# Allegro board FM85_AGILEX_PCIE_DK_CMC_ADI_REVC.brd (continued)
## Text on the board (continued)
User.45: R | PCB EDGE | Max component height bottom side | of PCIe card: .105/2.67mm | DWG NO. | SIZE | SCALE: 1/1 | REV | CAGE CODE | SHEET 2 OF 2 | PROPRIETARY NOTICE: | THIS DOCUMENT CONTAINS PROPRIETARY INFORMATION | OF ALTERA CORP. NEITHER THE DOCUMENT NOR SAID | PROPRIETARY INFORMATION SHALL BE PUBLISHED, | REPRODUCED, COPIED, DISCLOSED OR USED FOR ANY | PURPOSE OTHER THAN CONSIDERATION OF THIS DOCUMENT | WITHOUT THE EXPRESS WRITTEN PERMISSION OF A DULY | AUTHORIZED REPRESENTATIVE OF ALTERA CORPORATION | DEC .XXXX  .002 | 01 | INTEL CONFIDENTIAL | 3065 BOWERS AVE | SANTA CLARA | CALIF.  95051 | NOTES:(UNLESS OTHERWISE SPECIFIED) | (USE FOR OSP ONLY ) | 19. VIA PLUGGING REQUIREMENTS FOR TEST PAD VIA (EXCEPTION IS NOTE 23): | THE VIAS THAT ARE USED AS TEST PADS ARE REQUIRED TO BE PLUGGED ON THE SIDE THAT | IS OPPOSITE TO THE TEST PADS. THE PLUGGED MATERIAL HAS TO BE FILLED AT LEAST 40% | AND NO MORE THAN 90% OF THE VIA HEIGHT MEASURED FROM THE SIDE OPPOSITE TO THE TEST | PADS. IT IS REQUIRED THAT AIR SHALL NOT FLOW THROUGH FROM ONE END OF THE TEST PAD | VIA TO THE OTHER. THERE IS NO CONTINUOUS AIR GAP FROM ONE END TO THE OTHER END | OF THE VIA. THEY ARE REQUIRED TO BE STUFFED 3 TIMES AS FOLLOWS: | a. STUFF SOLDERMASK INTO THE VIAS FROM THE SIDE OPPOSITE THE TEST PADS. | b. SEAL THE VIAS USING SOLDERMASK ON THE SIDE OPPOSITE OF THE TEST PADS. | c. SEAL THE VIAS USING SOLDERMASK ON THE TEST PAD SIDE. | d. MAKE SURE THE SOLDERMASK IS TOTALLY CLEANED FROM ALL TEST PADS DURING | THE SOLDERMASK CLEANING PROCESS. | (IMPEDANCES SUBJECT TO CHANGE PER PROJECT REQUIREMENTS) | 20. REQUIRED REPORT OF PRODUCTION BOARDS: | EVERY 3 OR LESS LOTS AND 5000 OR LESS BOARDS, THE FOLLOWING TESTS ARE REQUIRED | BEFORE THE BOARDS ARE SHIPPED OUT. A COPY OF THE REPORT AND IMPEDANCE COUPON | TO BE SENT TO THE ENGINEER INVOLVED. | a. MEASURE THE FOLLOWING IMPEDANCES OF 30 RANDOMLY PICKED BOARDS: | i. SEE IMEPACNE TABLE FOR REQUIRED IMPEDANCES AND LAYERS TO BE MEASURED. | b. MEASURE THE Tg OF A PIECE OF MATERIAL FROM THE BOARD PANEL. THE Tg VALUE | HAS TO BE GREATER THAN .145. | c. CROSS SECTION A TEST PAD VIA FROM EACH CORNER OF ONE PCB (4 TEST PADS VIAS TOTAL). | THEY HAVE TO BE PICKED FROM TEST PAD VIAS THAT ARE CLOSE TO EACH CORNER. | PICTURES OF THE CROSS SECTION SHOWING THE STUFFING ARE REQUIRED | IN THE REPORT. MEASURE THE PERCENTAGE OF THE STUFFING IN THE PLUGGED VIAS, | COPPER FOIL + PLATING THICKNESS (TOP TO BOTTOM), COPPER PLATING | THICKNESS IN HOLE (6 LOCATIONS - 2 TOPS, 2 MIDDLES AND 2 BOTTOMS), | DIELECTRIC THICKNESS (CENTER AND CORNER), | TRACE PROPERTY (TOP WIDTH, BANDWIDTH AND THICKNESS), AND BOARD THICKNESS (WITHOUT SOLDERMASK). | d. MEASURE ALSO THE FOLLOWING ITEMS FROM ONE BOARD: | i .   OSP THICKNESS | i i . BOW AND TWIST (MAX AND MIN ) | i i i PEEL STRENGTH | iv.   CLEANLINESS TEST | v.    SOLDERABILITY | v i . THERMAL STRESS | vii.  THE DIMENSIONS OF ONE OF EVERY KIND OF HOLE | viii. THE OUTER DIMENSIONS OF THE BOARD | 1. MATERIALS: MEG*6. | 2. THIS DRAWING ALSO EXISTS ON ELECTRONIC MEDIA. | 3. FABRICATE PWB PER IPC-6012 CLASS 2 (LATEST REVISION). | 4. DIMENSIONING AND TOLERANCING PER ANSI Y14.5M. | 5. BOARD MUST BE UL 94V-0 APPROVED. | 6. BREAKOUT IN THE REGION OF THE TRACE/PAD JUNCTION SHALL NOT REDUCE THE | TRACE WIDTH BY MORE THAN 25% UNLESS OTHERWISE SPECIFIED. | 7. COPPER IN HOLES SHALL BE PER I PC - 6012(LATEST REVISION), CLASS 2. | 8. MAXIMUM BOARD WARPAGE IN ANY DIRECTION TO BE ,0075'/INCH, AS MEASURED BY | IPC-TM-650 TEST METHOD 2.4.22. | 9. VENDOR MARKING: VENDOR LOGO, UL MARKING AND DATECODE (4DIGIT WWYY)TO BE IN | ETCH ON SECONDARY (BOTTOM) SIDE AWAY FROM ALL BOARD FEATURES. | 10. FEATURE SIZE TOLERANCE: PLATED THRU HOLE PADS, INTERNAL PLANE CLEARANCES | (ANTIPADS) AND SURFACE MOUNT LAND PATTERNS SHALL BE +/- 10% OF THEIR CAD | DIMENSION WITH THE FOLLOWING EXCEPTION. ANY SMT LAND PATTERNS THAT HAVE | A FINISHED PAD WIDTH OR DIAMETER LESS THAN OR EQUAL TO .012' MUST USE THE | FOLLOWING TOLERANCE, +/-.001'. PCB VENDOR TO ADJUST ARTWORK TO | COMPENSATE FOR ETCH PROCESS. NOTE: THIS APPLIES TO ETCH SIZES BEFORE SOLDERMASK. | FURTHERMORE, FOR ETCH COMPENSATION, ONLY MINIMAL AMOUNT IS ALLOWED. | NO GEOMETRIES MAY BE ENLARGED FOR YIELD PURPOSES. | FINISHED PRODUCT MUST MATCH INTEL CAD DATA AS CLOSE AS POSSIBLE. | 11. FEATURE LOCATION TOLERANCE: ALL CONDUCTIVE FEATURES SHALL BE WITHIN | .008' DIAMETER TRUE POSITION REGARDLESS OF FEATURE SIZE (RFS). | 12. HOLE LOCATION TOLERANCE: PLATED THRU HOLES SHALL BE WITHIN .003' DIAMETER | TRUE POSITION AT MAXIMUM MATERIAL CONDITION (MMC ) . NON-PLATED HOLES <.200" | SHALL BE WITHIN .003' DIAMETER TRUE POSITION WITH RESPECT TO 0,0 DATUM. | NON-PLATED HOLES >.200 SHALL BE WITHIN .003' DIAMETER TRUE POSITION WITH | RESPECT TO DATUM. | 13. SILKSCREEN BOTH SIDES USING NON - CONDUCTIVE INK. COLOR: WHITE. | NO SILKSCREEN SHALL BE ON ANY EXPOSED COPPER PAD. TRIMMING ALLOWED EVEN | IF IMPACT TO LEGIBILITY. | 14. REMOVE ALL UNUSED PADS FROM INNER LAYERS. | 15. IMPEDANCE TO BE VERIFIED PER TABLE. IMPEDANCE COUPONS MUST REFLECT EACH | CONTROLLED IMPEDANCE FOR EACH LAYER. MEASUREMENTS MUST BE PERFORMED BY TDR. | IMPEDANCE REPORTING MUST SPECIFY EACH CONTROLLED IMPEDANCE GEOMETRY BY LAYER. | FULL AND ACCURATE REPORTING AND COUPONS MUST BE PROVIDED WITH BOARDS. RECORDS | MUST BE MAINTAINED BY SUPPLIER FOR REFERENCE BY DESIGN TEAM AS REQUIRED. | REPORTS PER LOT INFORMATION PER DATE CODE MUST BE AVAILABLE UPON REQUEST. | 16. SURFACE FINISH: ENIG (ENTHONE HT PLUS,FORMOCHEM F35,SHIKOKU F2 (LX) PLUX | THICKNESS SHALL BE 0.25 TO 0.50 MICRON). | 17. VIAS THAT ARE MASKED OVER BY DESIGN ARE PLUGGED, 30% TO 90%. VIAS WITH | SOLDERMASK OPENINGS ON TOP SIDE ARE BY DESIGN AND REMAIN OPEN. | EXCEPTION IS NOTE 23 | 18. SOLDERMASK BOTH SIDES, USING GREEN MATTE OR GLOSS SOLDERMASK PER I PC-SM-840. | SOLDERMASK PADS SHALL BE ENLARGED BY .004" OVERALL OR .002' PER SIDE | INCLUDING SOLDERMASK DEFINED PADS. SOLDERMASK DEFINED PADS SHALL STRICTLY FOLLOW | .002' OVERSIZE PER SIDE. NOTE 22 IS THE EXCEPTION. | NO CHANGE ALLOWED WITHOUT INTEL APPROVAL. | 25. ADD COPPER THIEVING WHERE NECESSARY, AND MAINTAIN A CLEARANCES OF 35 MILS TO ALL NETS. | 26. REMOVE THE THROUGH HOLE VIA PAD ON BOTTOM LAYER FOR THE PCIE GEN5 TO EDGE FINGER, | CXL TO MCIO  CONNECTOR AND QSFP-DD SIGNALS ROUTED ON LAYER16. | 27. IN EDGE FINGER REGION, SOME RESIDUAL METAL FROM THE PLATING TIE BAR IS PERMITTED TO | EXTEND NO MORE THAN 0.13 MM BEYOND THE BOTTOM OF THE EDGE FINGERS, INTO THE METAL | EXCLUSION REGION (BETWEEN THE EDGE FINGER AND CHAMFER REGION), "ETCH BACK" PROCESS | MAYBE REQUIRED TO DO THIS. | 21. EDGE CONNECTOR FINGERS:REQUIRE 30 MICRO INCHES HARD GOLD OVER 150-200 | MICRO INCHES OF NICKEL. | 22. FOR BGA "U2", ALL EXPOSED COPPER PADS, WHETHER SMD OR NSMD, MUST HAVE A 20 MILS PAD DIAMETER, | THEY ALL MUST BE EQUAL. | 23. FILL ALL 8MIL, 10MIL , 12MIL AND 20MIL DRILL HOLES USING NON - CONDUCTIVE EPOXY | 24. PLEASE ADD TEAR DROPS TO OUTER AND INNER LAYERS. | AND OVERPLATE WITH COPPER (VIPPO). | Impedance | *** SPECIAL NOTES*** | 1. INNER LAYER IMPEDANCE IS +/-7% (BOTH FOR MASS AND SAMPLE PRODUCTION) | 2. OUYER LAYER IMPEDANCE IS +/-10% (BOTH FOR MASS AND SAMPLE PRODUCTION) | 3. THROUGH HOLE VIA 8MILS DRILL : FINISHED HOLE WITH EPOXY AND PLATED SHUT ALMOST 6MIL | 4. MICRO VIA 1-3 & 16-18 : 10 MIL DRILL; FILLED MICRO-VIA WITH EPOXY. | Layer | 1 | 3 | 5 | 7 | 12 | 14 | 16 | 18 | IMPEDANCE TABLE (SEE SPECIAL NOTE) | - MUST NOT CUT LAYER 16 | INTERNAL GND PLANE LAYER 4 | INTERNAL GND PLANE LAYER 6 | INTERNAL GND PLANE LAYER 8 | INTERNAL PWR PLANE LAYER 9 | INTERNAL SIGNAL LAYER 5 | INTERNAL SIGNAL LAYER 7 | INTERNAL XXX LAYER 25 | INTERNAL XXX LAYER 26 | INTERNAL XXX LAYER 27 | INTERNAL XXX LAYER 28 | INTERNAL XXX LAYER 29 | INTERNAL XXX LAYER 30 | PRESS FIT | BACKDRILL DIAMETER | 26 | (D2=D1+8mils) | .050 CENTERS TYP. | MICRO VIA 17-18 | MICRO VIA 16-18 | THRU VIA 1-18 | .100 TABS TYP. | .025 NPTH TYP (3 PLCS) | .100 TYP. | L10/PLN - 1.0 Oz Cu | L11/PLN - 1.0 Oz Cu | L13/PLN - 0.5 Oz Cu | L14/SIG - 0.5 Oz Cu | L15/PLN - 0.5 Oz Cu | L16/SIG - 0.5 Oz Cu | L17/PLN - 0.5 Oz Cu | L18/BOT - 0.5 Oz Cu | L01/TOP - 0.5 Oz Cu 0.6 MILS THK | L12/SIG - 0.5 Oz Cu | L02/PLN - 0.5 Oz Cu | L03/SIG - 0.5 Oz Cu | L04/PLN - 0.5 Oz Cu | L05/SIG - 0.5 Oz Cu | L06/PLN - 0.5 Oz Cu | L07/SIG - 0.5 Oz Cu | L08/PLN - 1.0 Oz Cu | L09/PLN - 1.0 Oz Cu | MICRO VIA 1-3 | MICRO VIA 1-2 | 1078 Core  - 3 MILS THK | 1035 Core  - 2 MILS THK | Pre-1035HRC -2.3 MILS THK | COPPER PLATE 1.4MILS THK | Pre-1035HRC -2.7 MILS THK | Pre-1078LRC -2.7 MILS THK | Pre-1027/1035HRC -4.0 MILS THK | CHAMFER EDGE CONNECTOR | 1.3 MILS THK | SCALE: NONE | 0.6 MILS THK | 0.6MILS THK | 20.0 +/-2 | .051+/-.005 | 1.30+/-0.13 | SEE STACKUP | FOIL | LPHTE | HVLP | FIGURE | 42.5 OHM | (MILS) | 6.70 | 3.60 | 3.80 | 45 OHM | 5.85 | 3.20 | 3.50 | FINISHED_SIZE | 10.0 | 85 OHMS | Width/SP | 4.55/4.95 | 3.35/4.65 | 3.55/4.45 | DRILL CHART: L16_SIG6 to BOTTOM | ALL UNITS ARE IN MILS | DRILL CHART: L17_GND8 to BOTTOM | TOLERANCE_DRILL | +0.0/-10.0 | 3.20/4.00 | 3.50/4.00 | DETAIL "B" | 90 OHMS | 4.00/5.00 | 3.10/5.90 | 3.35/5.65 | PLATED | 3.00/4.00 | NECKDOWN | QTY | 46 | 246 | 85 & 90 OHMS | TOOLING HOLE SIZE/LOCATION DETERMINED BY FAB VENDOR (4 PLCS) | 8.0 | 12.0 | 20.0 | 31.0 | 32.0 | 40.0 | 41.339 | 45.0 | 47.0 | 61.0 | 71.0 | 97.0 | 125.0 | 181.102 | 49.0 | 51.0 | 118.0 | 33.46x25.59 | 51.181x23.622 | 97.0x48.0 | DRILL CHART: TOP to L03_SIG1 | DRILL CHART: TOP to BOTTOM | DRILL CHART: TOP to L02_GND1 | +0.0/-8.0 | +0.0/-12.0 | +3.0/-3.0 | +1.969/-1.969 | +5.0/-0.0 | +2.0/-2.0 | NON-PLATED | 377 | 8057 | 194 | 456 | 786 | 101 | 6 | 8 | 24 | 10 | 2 | 4 | 178 | Thickness After plating | (not including solder mask) | .0622  +/-.005 | + | - | 100-0321309-01 | DETAIL | (CROSS SECTION) | AGILEX I-SERIES FPGA DEVKIT | PRIMARY SIDE SHOWN | SECONDARY SIDE SHOWN | UNIT : INCHES[MM] | BOTTOM SIDE SHOWN | TOP SIDE SHOWN | D | N/A | B | A
